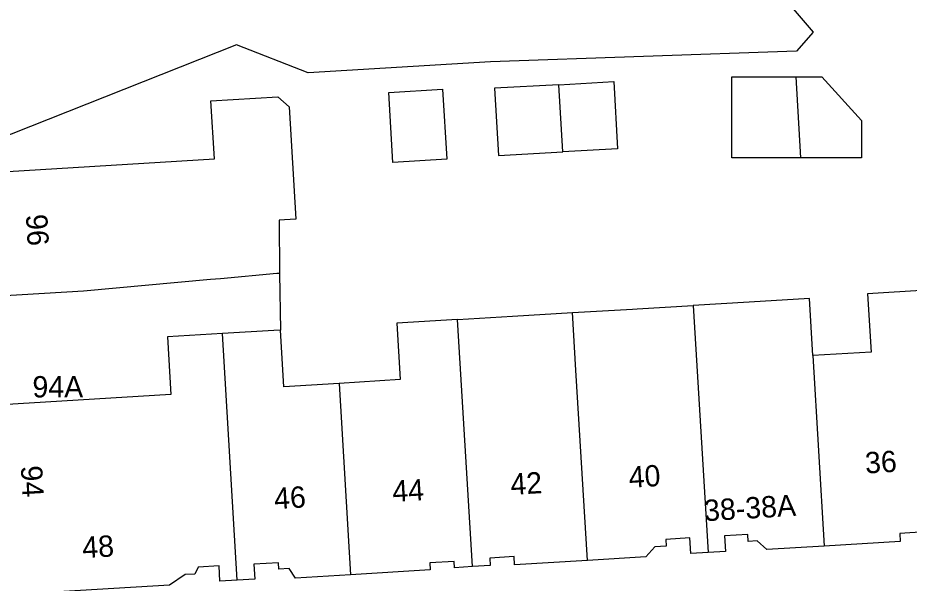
# Model space of a CAD drawing. Extents: x 160861 to 161308, y 384024 to 384878.
# Drawn here: x 161136.59 to 161178.37, y 384308.47 to 384334.96 of the extents above; entities that cross this region are included whole.
import ezdxf

# ---------------------------------------------------------------- set-up
doc = ezdxf.new("R2010")
doc.units = 0
doc.layers.add('IMGEO_Pand', color=7, linetype='Continuous')
doc.layers.add('IMGEO_Pand_nummerreeks', color=7, linetype='Continuous')

msp = doc.modelspace()

# ---------------------------------------------------------------- linework, layer by layer
at = {"layer": 'IMGEO_Pand'}
for points in [[(161160.436, 384348.067), (161161.693, 384348.538), (161173.878, 384334.3), (161173.085, 384333.395), (161158.754, 384332.896), (161150.199, 384332.38), (161146.843, 384333.693), (161136.28, 384329.511), (161133.903, 384328.57)], [(161161.954, 384331.83), (161164.524, 384331.974), (161164.7, 384328.825), (161162.143, 384328.682)], [(161173.298, 384328.41), (161170.066, 384328.41), (161170.066, 384332.202), (161173.07, 384332.202)], [(161173.298, 384328.41), (161173.07, 384332.202)], [(161173.07, 384332.202), (161174.283, 384332.202), (161176.14, 384330.156), (161176.14, 384328.41), (161173.298, 384328.41)], [(161156.696, 384328.335), (161154.178, 384328.186), (161153.983, 384331.472), (161156.502, 384331.621), (161156.696, 384328.335)], [(161161.954, 384331.83), (161158.944, 384331.663), (161159.12, 384328.514), (161162.143, 384328.682)], [(161162.143, 384328.682), (161161.954, 384331.83)], [(161134.328, 384327.656), (161145.813, 384328.357), (161145.647, 384331.075), (161148.782, 384331.267), (161149.311, 384330.799), (161149.632, 384325.53), (161149.098, 384325.497), (161148.845, 384325.482), (161148.867, 384322.987)], [(161148.867, 384322.987), (161148.742, 384322.976), (161146.096, 384322.738), (161145.623, 384322.696), (161139.673, 384322.161), (161134.682, 384321.856)], [(161148.867, 384322.987), (161148.901, 384320.327)], [(161179.181, 384322.198), (161176.421, 384322.032), (161176.586, 384319.304), (161173.854, 384319.139)], [(161173.854, 384319.139), (161173.693, 384321.816), (161170.865, 384321.646), (161168.251, 384321.488)], [(161157.206, 384320.832), (161159.784, 384320.987), (161162.594, 384321.156)], [(161162.594, 384321.156), (161165.408, 384321.317), (161165.616, 384321.33), (161168.251, 384321.488)], [(161163.29, 384309.533), (161162.756, 384318.447), (161162.594, 384321.156)], [(161168.251, 384321.488), (161168.945, 384309.911)], [(161157.206, 384320.832), (161154.36, 384320.66), (161154.52, 384318.008), (161151.652, 384317.835)], [(161157.9, 384309.247), (161157.206, 384320.832)], [(161148.901, 384320.327), (161148.594, 384320.309), (161146.188, 384320.164)], [(161151.652, 384317.835), (161149.06, 384317.679), (161148.901, 384320.327)], [(161146.188, 384320.164), (161143.603, 384320.008), (161143.765, 384317.312), (161135.057, 384316.787)], [(161146.882, 384308.616), (161146.188, 384320.164)], [(161173.854, 384319.139), (161174.39, 384310.207)], [(161151.652, 384317.835), (161152.189, 384308.868)], [(161174.39, 384310.207), (161171.708, 384310.045), (161171.252, 384310.45), (161170.825, 384310.424), (161170.805, 384310.759), (161169.711, 384310.694), (161169.756, 384309.96), (161168.945, 384309.911)], [(161179.879, 384310.537), (161179.152, 384310.493), (161179.129, 384310.87), (161177.932, 384310.798), (161177.955, 384310.422), (161174.39, 384310.207)], [(161168.945, 384309.911), (161168.134, 384309.862), (161168.09, 384310.588), (161166.967, 384310.52), (161166.986, 384310.201), (161166.453, 384310.169), (161166.036, 384309.698), (161163.29, 384309.533)], [(161152.189, 384308.868), (161149.616, 384308.713), (161149.318, 384309.164), (161148.827, 384309.135), (161148.81, 384309.424), (161147.655, 384309.354), (161147.696, 384308.665), (161146.882, 384308.616)], [(161157.9, 384309.247), (161157.068, 384309.197), (161157.048, 384309.485), (161155.904, 384309.419), (161155.924, 384309.093), (161152.189, 384308.868)], [(161163.29, 384309.533), (161159.879, 384309.327), (161159.856, 384309.715), (161158.711, 384309.646), (161158.732, 384309.297), (161157.9, 384309.247)], [(161146.882, 384308.616), (161146.068, 384308.567), (161146.024, 384309.286), (161145.049, 384309.228), (161144.884, 384308.897), (161144.439, 384308.87), (161143.7, 384308.382), (161136.93, 384307.974)]]:
    msp.add_lwpolyline(points, dxfattribs=at)

# ---------------------------------------------------------------- texts
at = {"layer": 'IMGEO_Pand_nummerreeks'}
for s, rotation, p in [('96', 273.4948, (161136.97, 384325.735)), ('36', 3.4452, (161176.332, 384313.605)), ('40', 3.4435, (161165.256, 384312.938)), ('94', 273.2485, (161136.733, 384313.957)), ('42', 3.4435, (161159.71, 384312.604)), ('44', 3.4452, (161154.174, 384312.271)), ('46', 3.4452, (161148.634, 384311.937)), ('38-38A', 3.4549, (161168.788, 384311.371)), ('48', 3.2487, (161139.641, 384309.643))]:
    msp.add_text(s, height=1, rotation=rotation, dxfattribs=at).set_placement(p)
msp.add_text('94A', height=1, dxfattribs=at).set_placement((161137.279, 384317.175))

doc.saveas('drawing.dxf')
